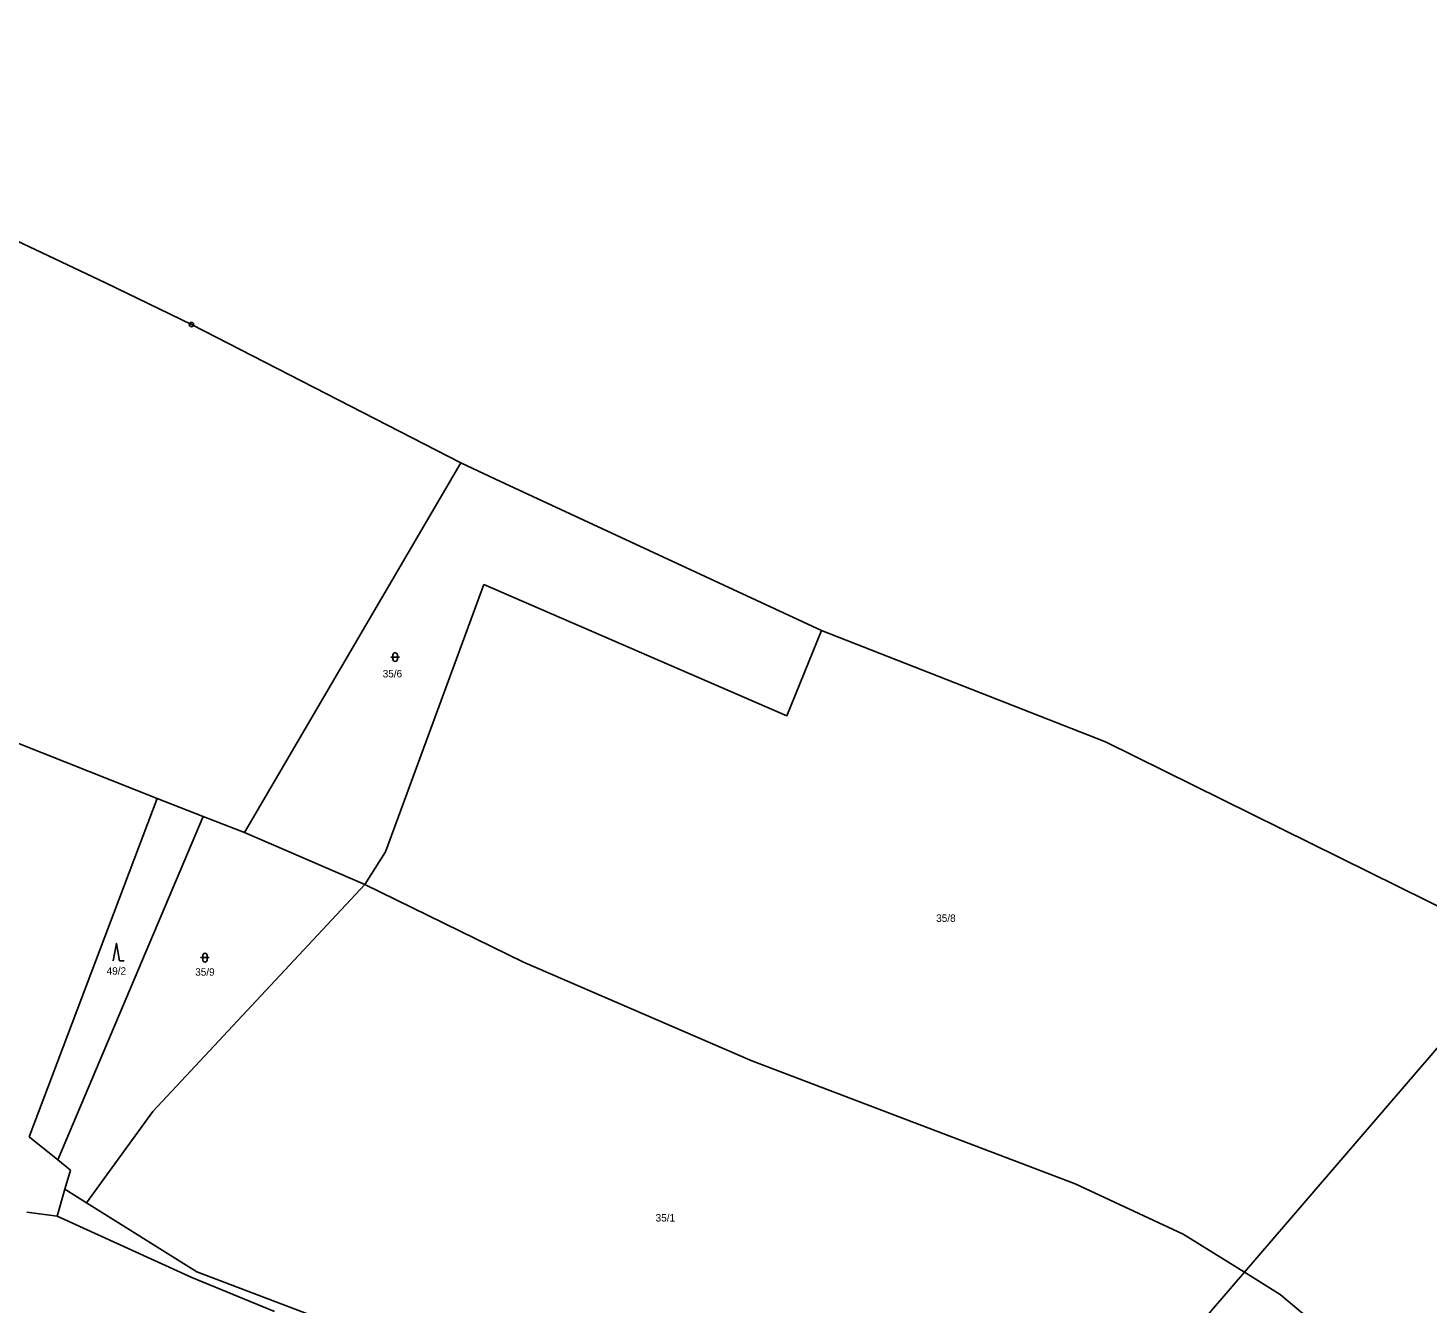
# Model space of a CAD drawing. Extents: x -601877 to -599786, y -1122905 to -1121218.
# Drawn here: x -600496.9 to -600177.9, y -1121670.7 to -1121380.1 of the extents above; entities that cross this region are included whole.
import ezdxf
from ezdxf.enums import TextEntityAlignment as Align

# ---------------------------------------------------------------- set-up
doc = ezdxf.new("R2010")
doc.units = 0
doc.header["$LTSCALE"] = 0.68
for name, color, linetype, lineweight in [('1', 7, 'Continuous', 25), ('3', 7, 'Continuous', 25), ('8', 7, 'Continuous', 25)]:
    doc.layers.add(name, color=color, linetype=linetype, lineweight=lineweight)
doc.layers.add('2', color=7, linetype='Continuous')

msp = doc.modelspace()

# ---------------------------------------------------------------- linework, layer by layer
at = {"layer": '1'}
for p, q in [((-600479.25, -1121438.23), (-600459.64, -1121447.72)), ((-600459.64, -1121447.72), (-600398.28, -1121479.24)), ((-600398.28, -1121479.24), (-600447.6, -1121563.49)), ((-600398.28, -1121479.24), (-600390.34, -1121482.93)), ((-600316.09, -1121517.46), (-600390.34, -1121482.93)), ((-600393.06, -1121506.98), (-600415.4, -1121567.91)), ((-600324.01, -1121536.86), (-600393.06, -1121506.98)), ((-600316.09, -1121517.46), (-600324.01, -1121536.86)), ((-600251.37, -1121542.84), (-600316.09, -1121517.46)), ((-600508.89, -1121539.27), (-600467.47, -1121555.73)), ((-600171.3, -1121582.36), (-600251.37, -1121542.84)), ((-600467.47, -1121555.73), (-600496.63, -1121632.84)), ((-600467.47, -1121555.73), (-600457.02, -1121559.81)), ((-600490.14, -1121638.05), (-600457.02, -1121559.81)), ((-600457.02, -1121559.81), (-600447.6, -1121563.49)), ((-600447.6, -1121563.49), (-600420.18, -1121575.3)), ((-600415.4, -1121567.91), (-600420.18, -1121575.3)), ((-600420.18, -1121575.3), (-600468.49, -1121627.1)), ((-600420.18, -1121575.3), (-600383.99, -1121593.02)), ((-600219.7, -1121663.67), (-600156.33, -1121589.98)), ((-600383.99, -1121593.02), (-600331.97, -1121615.48)), ((-600331.97, -1121615.48), (-600258.28, -1121643.54)), ((-600468.49, -1121627.1), (-600483.55, -1121647.85)), ((-600496.63, -1121632.84), (-600490.14, -1121638.05)), ((-600487.24, -1121640.44), (-600490.14, -1121638.05)), ((-600488.5, -1121644.74), (-600487.24, -1121640.44)), ((-600490.27, -1121650.88), (-600488.5, -1121644.74)), ((-600483.55, -1121647.85), (-600488.5, -1121644.74)), ((-600258.28, -1121643.54), (-600233.64, -1121654.99)), ((-600458.44, -1121663.63), (-600483.55, -1121647.85)), ((-600497.18, -1121649.98), (-600490.27, -1121650.88)), ((-600490.27, -1121650.88), (-600459.6, -1121664.93)), ((-600233.64, -1121654.99), (-600219.7, -1121663.67)), ((-600381.71, -1121692.64), (-600458.44, -1121663.63)), ((-600290.03, -1121745.45), (-600219.7, -1121663.67)), ((-600219.7, -1121663.67), (-600211.53, -1121668.75)), ((-600459.6, -1121664.93), (-600440.75, -1121672.67)), ((-600211.53, -1121668.75), (-600184.91, -1121691.09))]:
    msp.add_line(p, q, dxfattribs=at)
msp.add_lwpolyline([(-600602.67, -1121380.11), (-600523.89, -1121417.05), (-600479.25, -1121438.23)], dxfattribs=at)
at = {"layer": '3'}
for p, q in [((-600414.231, -1121523.491), (-600412.229, -1121523.491)), ((-600413.731, -1121522.991), (-600413.731, -1121523.992)), ((-600412.729, -1121523.992), (-600412.729, -1121522.991)), ((-600476.02, -1121592.75), (-600475.024, -1121592.75)), ((-600457.591, -1121591.991), (-600455.589, -1121591.991)), ((-600457.091, -1121591.491), (-600457.091, -1121592.492)), ((-600456.089, -1121592.492), (-600456.089, -1121591.491))]:
    msp.add_line(p, q, dxfattribs=at)
msp.add_lwpolyline([(-600476.02, -1121592.75), (-600476.77, -1121588.75), (-600477.52, -1121592.75)], dxfattribs=at)
for centre, start, end in [((-600413.23, -1121522.9909), 0, 180), ((-600413.23, -1121523.9909), 180, 359.98789), ((-600456.59, -1121591.4909), 0, 180), ((-600456.59, -1121592.4909), 180, 359.98789)]:
    msp.add_arc(centre, 0.5, start, end, dxfattribs=at)
at = {"layer": '8'}
for radius in [0.5, 0.0303]:
    msp.add_circle((-600459.64, -1121447.7199), radius, dxfattribs=at)

# ---------------------------------------------------------------- texts
at = {"layer": '2'}
for s, p in [('35/6', (-600413.859, -1121528.125)), ('35/8', (-600287.729, -1121583.845)), ('49/2', (-600476.769, -1121595.875)), ('35/9', (-600456.589, -1121596.115)), ('35/1', (-600351.669, -1121652.145))]:
    msp.add_text(s, height=1.7, dxfattribs=at).set_placement(p, align=Align.CENTER)

doc.saveas('drawing.dxf')
